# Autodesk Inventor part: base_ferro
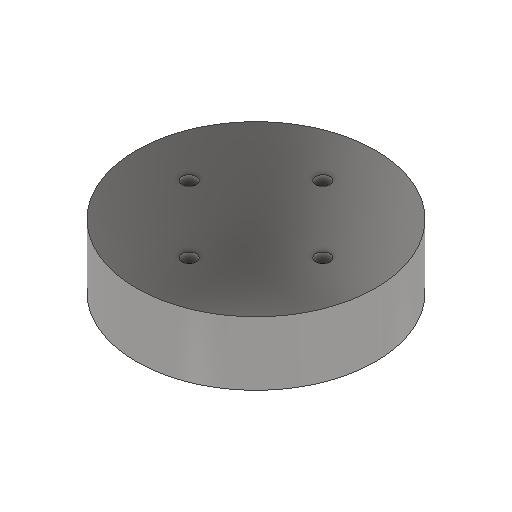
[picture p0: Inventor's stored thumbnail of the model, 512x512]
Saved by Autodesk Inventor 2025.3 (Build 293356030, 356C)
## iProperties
Created: 2026-01
Part Number: base_ferro
Material: Acciaio
Document SubType Name: Modeling
Designer: Ryzen5700u
Density: 7.85 g/cm^3
Appearance: Acciaio - Lucido
Mass: 7039.17 g
Surface Area: 726.938 cm^2
Volume: 896.709 cm^3
Author: Ryzen5700u
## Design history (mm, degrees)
sketch "Schizzo1"
  geometry: C1 r 50 at (0, 0); 1 further point
  constraints: 1 centre point, 1 coincident
  dimensions: "d0" = 100 diameter of C1
extrude "Estrusione1" new body sketch "Schizzo1" distance "d1" = 40; taper "d2" = 0 deg
sketch "Schizzo3"
  geometry: L1 (0, 0)-(42, 0)
  constraints: 2 end point, 1 horizontal
  dimensions: "d14" = 42 distance of L1.start L1.end
hole "Foro2" sketch "Schizzo3" at (42, 0) diameter "d15" = 5.3; stored, may be unused: countersink angle "d19" = 90 deg, drill point angle "d21" = 118 deg; dims "d16" = 6, "d17" = 9, "d18" = 15, "d20" = 8
pattern_circular "Serie circolare2" dims angle "d23" = 360 deg
sketch "Schizzo4"
  geometry: C1 r 75 at (0, 0); C2 r 50 at (0, 0) reference; 1 further point
  constraints: 1 centre point, 1 coincident
  dimensions: "d25" = 150 diameter of C1
extrude "Estrusione2" join sketch "Schizzo4" stored distance "d26" = 10; taper "d27" = 0 deg
node "Solido1"
